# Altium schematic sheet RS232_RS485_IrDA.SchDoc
size A4; Revision: C.2
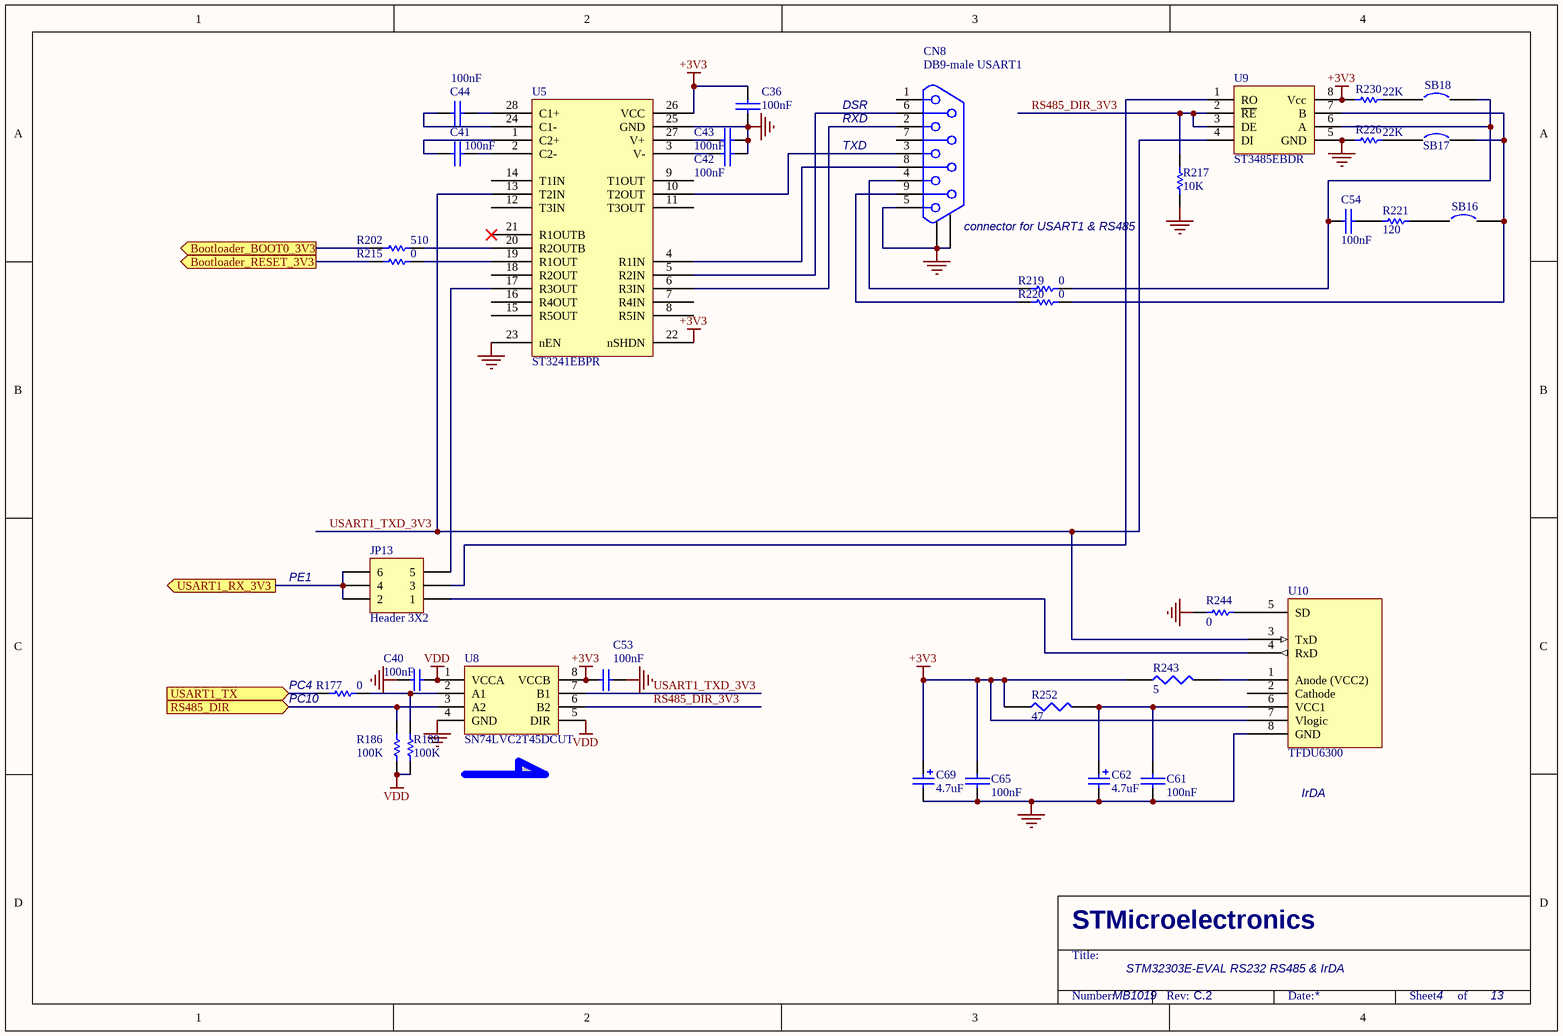
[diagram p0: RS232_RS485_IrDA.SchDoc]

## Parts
C36  100nF  [0603C]
C40  100nF  [0603C]
C41  100nF  [0603C]
C42  100nF  [0603C]
C43  100nF  [0603C]
C44  100nF  [0603C]
C53  100nF  [0603C]
C54  100nF  [0603C]
C61  100nF  [0603C]
C62  4.7uF  [TAN-A]
C65  100nF  [0603C]
C69  4.7uF  [TAN-A]
CN8  DB9-male USART1  [DB9/M]
JP13  Header 3X2  [2*3P]
R177  0  [0603R]
R186  100K  [0603R]
R189  100K  [0603R]
R202  510  [0603R]
R215  0  [0603R]
R217  10K  [0603R]
R219  0  [0603R]
R220  0  [0603R]
R221  120  [0603R]
R226  22K  [0603R]
R230  22K  [0603R]
R243  5  [0603R]
R244  0  [0603R]
R252  47  [0603R]
SB16  (no value)  [JP2_SMD]
SB17  (no value)  [JP2_SMD]
SB18  (no value)  [JP2_SMD]
U5  ST3241EBPR  [SSOP28]
U8  SN74LVC2T45DCUT  [VSSOP8]
U9  ST3485EBDR  [SO8]
U10  TFDU6300  [IR_VISHAY3]

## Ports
Bootloader_BOOT0_3V3 (out), Bootloader_RESET_3V3 (out), RS485_DIR (in), USART1_RX_3V3 (out), USART1_TX (in)

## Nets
+3V3: C36.2 C53.2 C65.1 C69.1 R230.2 R243.1 R252.1 U5.22(nSHDN) U5.26(VCC) U8.8(VCCB) U9.8(Vcc) U10.7(Vlogic)
GND: C36.1 C40.1 C42.2 C43.2 C53.1 C61.2 C62.2 C65.2 C69.2 CN8.0 CN8.5 R217.1 R226.2 R244.2 U5.23(nEN) U5.25(GND) U8.4(GND) U9.5(GND) U10.8(GND)
VDD: C40.2 R186.2 R189.2 U8.1(VCCA) U8.5(DIR)
Bootloader_BOOT0_3V3: R202.1 ; port Bootloader_BOOT0_3V3
Bootloader_RESET_3V3: R215.1 ; port Bootloader_RESET_3V3
RS485_DIR: R186.1 U8.3(A2) ; port RS485_DIR
RS485_DIR_3V3: R217.2 U8.6(B2) U9.2(~{RE}) U9.3(DE)
USART1_RX_3V3: JP13.2 JP13.4 JP13.6 ; port USART1_RX_3V3
USART1_TX: R177.2 ; port USART1_TX
USART1_TXD_3V3: U5.13(T2IN) U8.7(B1) U9.4(DI) U10.3(TxD)
NetC41_1: C41.1 U5.1(C2+)
NetC41_2: C41.2 U5.2(C2-)
NetC42_1: C42.1 U5.3(V-)
NetC43_1: C43.1 U5.27(V+)
NetC44_1: C44.1 U5.24(C1-)
NetC44_2: C44.2 U5.28(C1+)
NetC54_1: C54.1 R221.1
NetC54_2: C54.2 R219.1 SB18.2 U9.6(A)
NetC61_1: C61.1 C62.1 R252.2 U10.6(VCC1)
NetCN8_2: CN8.2 U5.6(R3IN)
NetCN8_3: CN8.3 U5.10(T2OUT)
NetCN8_4: CN8.4 R219.2
NetCN8_6: CN8.6 U5.5(R2IN)
NetCN8_8: CN8.8 U5.4(R1IN)
NetCN8_9: CN8.9 R220.2
NetJP13_1: JP13.1 U10.4(RxD)
NetJP13_3: JP13.3 U9.1(RO)
NetJP13_5: JP13.5 U5.17(R3OUT)
NetR177_1: R177.1 R189.1 U8.2(A1)
NetR202_2: R202.2 U5.20(R2OUTB)
NetR215_2: R215.2 U5.19(R1OUT)
NetR220_1: R220.1 SB16.2 SB17.2 U9.7(B)
NetR221_2: R221.2 SB16.1
NetR226_1: R226.1 SB17.1
NetR230_1: R230.1 SB18.1
NetR243_2: R243.2 U10.1(Anode_(VCC2))
NetR244_1: R244.1 U10.5(SD)

Not connected (* = marked no-connect by the designer): CN8 1 7; U5 7(R4IN) 8(R5IN) 9(T1OUT) 11(T3OUT) 12(T3IN) 14(T1IN) 15(R5OUT) 16(R4OUT) 18(R2OUT) 21(R1OUTB)*; U10 2(Cathode)

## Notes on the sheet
- DSR
- RXD
- TXD
- (near CN8) connector for USART1 & RS485
- PE1
- (near R177) PC4
- (near R177) PC10
- IrDA
- STM32303E-EVAL RS232 RS485 & IrDA
- MB1019
- 4
- 13

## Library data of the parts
C36 C41-C44 C54 C61 C65 = CAP: Capacitor
C40 C53 = CAP: Capacitor; Value: 100pF
C62 C69 = Cap Pol1: Polarized Capacitor (Radial); Value: 100pF
CN8 = DB9
JP13 = Header 3X2: Header, 3-Pin, Dual row
R177 = res1: Resistor; Value: 1K
R186 R189 R202 R215 R217 R219-R221 R226 R230 R244 = Res1: Resistor; Value: 1K
R243 R252 = RES1
SB16-SB18 = Circuit Breaker
U5 = ST3241
U9 = ST485ABDR
U10 = TFDU4300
